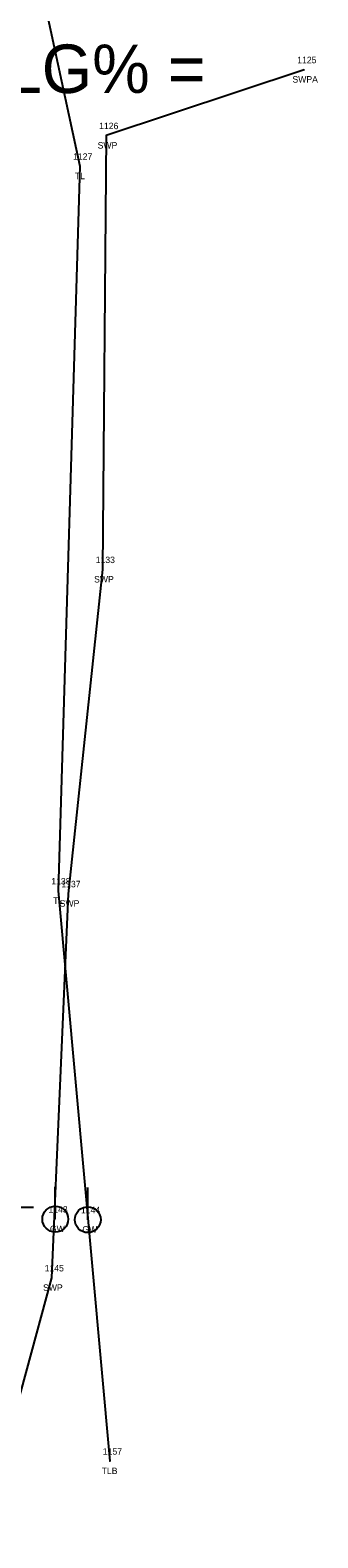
# Model space of a CAD drawing. Extents: x 2432632 to 2433497, y 684847 to 688233.
# Drawn here: x 2433185.1 to 2433229.6, y 686062.5 to 686295.7 of the extents above; entities that cross this region are included whole.
import ezdxf

# ---------------------------------------------------------------- set-up
doc = ezdxf.new("R2010")
doc.units = 0
for name, color, linetype in [('RD_EX_H2O', 7, 'Continuous'), ('RD_EX_H2O_txCode', 7, 'Continuous'), ('RD_EX_UT', 7, 'Continuous'), ('RD_EX_UT_txCode', 7, 'Continuous'), ('RD_EX_VEG', 7, 'Continuous'), ('RD_EX_VEG_txCode', 7, 'Continuous'), ('RD_HC_Data', 7, 'Continuous'), ('RD_SMD_Locator', 7, 'Continuous')]:
    doc.layers.add(name, color=color, linetype=linetype)

msp = doc.modelspace()

# ---------------------------------------------------------------- linework, layer by layer
at = {"layer": 'RD_EX_H2O'}
msp.add_lwpolyline([(2433227.48, 686289.61), (2433196.85, 686279.41), (2433196.3, 686212.3), (2433190.98, 686162.16), (2433188.39, 686102.75), (2433180.42, 686073.48), (2433172.96, 686068.93), (2433166.53, 686062.55)], dxfattribs=at)
at = {"layer": 'RD_EX_UT'}
for p, q in [((2433188.98, 686111.84), (2433188.98, 686116.84)), ((2433194, 686111.75), (2433194, 686116.75)), ((2433181.98, 686113.69), (2433185.62, 686113.69))]:
    msp.add_line(p, q, dxfattribs=at)
for centre in [(2433188.98, 686111.84), (2433194, 686111.75)]:
    msp.add_circle(centre, 2, dxfattribs=at)
at = {"layer": 'RD_EX_VEG'}
msp.add_lwpolyline([(2433166.25, 688082.87), (2433111.93, 687876.69), (2433067.75, 687703.46), (2433065.05, 687678.03), (2433052.74, 687645.62), (2433005.45, 687469.88), (2432979.96, 687326.61), (2432966.8, 687267.34), (2432959.05, 687210.65), (2432959.25, 687071.62), (2432974.82, 687014.37), (2432998.13, 686938.9), (2433012.99, 686878.7), (2433054.45, 686782.35), (2433123.54, 686586.06), (2433129.82, 686546.35), (2433158.34, 686434.26), (2433192.79, 686274.67), (2433189.42, 686162.6), (2433197.4, 686074.41)], dxfattribs=at)
at = {"layer": 'RD_SMD_Locator'}
for centre in [(2433227.48, 686289.61), (2433196.85, 686279.41), (2433192.79, 686274.67), (2433196.3, 686212.3), (2433189.42, 686162.6), (2433190.98, 686162.16), (2433188.39, 686102.75), (2433197.4, 686074.41)]:
    msp.add_circle(centre, 0.001, dxfattribs=at)

# ---------------------------------------------------------------- texts
at = {"layer": 'RD_EX_H2O_txCode'}
for s, p in [('1125', (2433226.42, 686290.61)), ('SWPA', (2433225.68, 686287.61)), ('1126', (2433195.76, 686280.41)), ('SWP', (2433195.53, 686277.41)), ('1133', (2433195.23, 686213.3)), ('SWP', (2433194.98, 686210.3)), ('1137', (2433189.91, 686163.16)), ('SWP', (2433189.66, 686160.16)), ('1145', (2433187.33, 686103.75)), ('SWP', (2433187.08, 686100.75))]:
    msp.add_text(s, height=1, dxfattribs=at).set_placement(p)
at = {"layer": 'RD_EX_UT_txCode'}
for s, p in [('1143', (2433187.92, 686112.84)), ('1144', (2433192.94, 686112.75)), ('GW', (2433188.14, 686109.84)), ('GW', (2433193.16, 686109.75))]:
    msp.add_text(s, height=1, dxfattribs=at).set_placement(p)
at = {"layer": 'RD_EX_VEG_txCode'}
for s, p in [('1127', (2433191.73, 686275.67)), ('TL', (2433192.02, 686272.67)), ('1138', (2433188.36, 686163.6)), ('TL', (2433188.65, 686160.6)), ('1157', (2433196.33, 686075.41)), ('TLB', (2433196.15, 686072.41))]:
    msp.add_text(s, height=1, dxfattribs=at).set_placement(p)
at = {"layer": 'RD_HC_Data'}
msp.add_text('P.T. - LG% = ', height=7.5, dxfattribs=at).set_placement((2433154, 686286))

doc.saveas('drawing.dxf')
